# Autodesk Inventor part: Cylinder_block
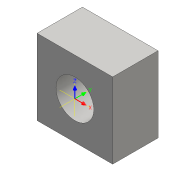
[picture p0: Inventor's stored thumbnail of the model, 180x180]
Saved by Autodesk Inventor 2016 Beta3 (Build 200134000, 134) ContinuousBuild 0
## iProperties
Created: 2016-03
Part Number: Cylinder_block
Material: Generic
Document SubType Name: Modeling
Designer: Gaurav
Density: 1 g/cm^3
Appearance: Default
Author: Gaurav
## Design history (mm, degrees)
sketch "Sketch1"
  geometry: L1 (25, 25)-(-25, 25); L2 (-25, 25)-(-25, -25); L3 (-25, -25)-(25, -25); L4 (25, -25)-(25, 25); L5 (25, 25)-(-25, -25); L6 (-25, 25)-(25, -25); C1 r 12.5 at (0, 0); 1 further point
  constraints: 12 end point, 2 midpoint, 2 parallel, 1 centre point, 1 coincident, 1 horizontal, 1 perpendicular
  dimensions: "d0" = 25 diameter of C1; "d1" = 50 distance of L3.end L2.end; "d2" = 50 distance of L2.end L1.end
extrude "Extrusion1" new body sketch "Sketch1" distance "d3" = 30; taper "d4" = 0 deg
body "Solid1"
other parameters: "d5" = 0, "d6" = 0, "d7" = 0, "d8" = 0, "d9" = 0, "d10" = 0
